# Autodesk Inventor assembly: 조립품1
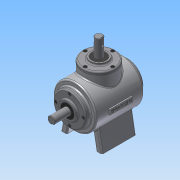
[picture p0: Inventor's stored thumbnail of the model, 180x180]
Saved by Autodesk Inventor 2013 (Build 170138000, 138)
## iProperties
Created: 2015-01
Part Number: 조립품1
Document SubType Name: Assembly
Designer: Administrator
Author: Administrator
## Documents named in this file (15)
- C:\Users\Administrator\Desktop\450106V1019\조립품1.iam
- C:\Users\Administrator\Desktop\450106V1019\본체.ipt
- C:\Users\Administrator\Desktop\450106V1019\M4.ipt
- C:\Users\Administrator\Desktop\450106V1019\메인 베벨기어.ipt
- C:\Users\Administrator\Desktop\450106V1019\메인 축.ipt
- 메인 축.ipt
- C:\Users\Administrator\Desktop\450106V1019\베어링 6203.ipt
- C:\Users\Administrator\Desktop\450106V1019\서브 베벨기어.ipt
- C:\Users\Administrator\Desktop\450106V1019\서브 축.ipt
- 서브 축.ipt
- C:\Users\Administrator\Desktop\450106V1019\오일실.ipt
- C:\Users\Administrator\Desktop\450106V1019\커버.ipt
- C:\Users\Administrator\Desktop\450106V1019\커버2.ipt
- C:\Users\Administrator\Desktop\450106V1019\키 4x4.ipt
- C:\Users\Administrator\Desktop\450106V1019\키 5x5.ipt
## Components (12 placed, 1 different names)
1. M4:2
2. M4:4
3. M4:5
4. M4:6
5. M4:1
6. M4:7
7. M4:8
8. M4:9
9. M4:3
10. M4:10
11. M4:11
12. M4:12
